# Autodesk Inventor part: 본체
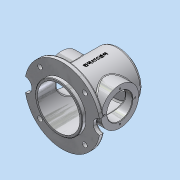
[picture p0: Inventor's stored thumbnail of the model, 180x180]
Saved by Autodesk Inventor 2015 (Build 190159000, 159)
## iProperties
Created: 2018-04
Part Number: 본체
Material: 알루미늄 6061
Document SubType Name: Modeling
Designer: Administrator
Density: 2.7 g/cm^3
Appearance: 알루미늄 - 평지
Mass: 1145.58 g
Surface Area: 1204.98 cm^2
Volume: 424.287 cm^3
Author: Administrator
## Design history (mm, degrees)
sketch "스케치1"
  geometry: 1 further point
sketch "스케치2"
  geometry: L1 (0, -64)-(0, 64); L2 (0, 64)-(-50, 64); L3 (-50, 64)-(-50, -64); L4 (-50, -64)-(0, -64); 2 further points
  constraints: 8 end point, 3 perpendicular, 1 coincident, 1 midpoint, 1 vertical
  dimensions: "d0" = 50 distance of L3.end L1.start; "d1" = 128 distance of L2.end L3.end
revolve "회전1" sketch "스케치2" stored, may be unused: angle "d2" = 90 deg
node "작업 평면1"
sketch "스케치3"
  geometry: C1 r 80 at (0, 0); 1 further point
  constraints: 1 centre point, 1 coincident
  dimensions: "d4" = 160 diameter of C1
extrude "돌출1" join sketch "스케치3" distance "d5" = 10; taper "d6" = 0 deg
sketch "스케치4"
  geometry: A1 r 80 centre (0, 0) between (-80, 0) and (80, 0) reference
  constraints: 2 horizontal alignment, 2 point on circle
hole "구멍1" sketch "스케치4" at (80, 0), (-80, 0) diameter "d7" = 30; stored, may be unused: countersink angle "d11" = 90 deg, drill point angle "d13" = 118 deg; dims "d8" = 6, "d9" = 4, "d10" = 2, "d12" = 8
sketch "스케치5" dims "d14" = 135
  geometry: L1 (0, 0)-(0, 102.247); L2 (0, 0)-(-71.221, 71.221); A1 r 80 centre (0, 0) between (-78.594, -14.934) and (78.594, -14.934) reference; 1 further point
  constraints: 4 end point, 1 coincident, 1 point on line, 1 vertical, 3 other
  dimensions: "d15" = 45 deg angle of L2 L1
hole "구멍2" sketch "스케치5" at (-47.73, 47.73) diameter "d16" = 10; stored, may be unused: countersink angle "d20" = 90 deg, drill point angle "d22" = 118 deg; dims "d17" = 6, "d18" = 4, "d19" = 2, "d21" = 8
fillet "모깎기1" dims "d26" = 3
sketch "스케치6"
  geometry: C1 r 50 at (0, 0) reference; C2 r 40 at (0, 0)
  constraints: 1 centre point, 1 coincident
  dimensions: "d27" = 80 diameter of C2
extrude "돌출2" join sketch "스케치6" distance "d28" = 5; taper "d29" = 0 deg
fillet "모깎기2" dims "d30" = 3
sketch "스케치7"
  geometry: L1 (0, -64)-(0, 69); L2 (0, 69)-(-27, 69); L3 (-27, 69)-(-27, 56); L4 (-27, 56)-(-45, 56); L5 (-45, 56)-(-45, -64); L6 (-45, -64)-(0, -64); L7 (40, 69)-(-40, 69) reference; 1 further point
  constraints: 12 end point, 5 perpendicular, 1 midpoint, 1 point on line, 1 vertical
  dimensions: "d31" = 133 distance of L1.start L1.end; "d32" = 45 distance of L5.end L1.start; "d33" = 27 distance of L1.end L2.end; "d34" = 120 distance of L4.end L5.end
revolve "회전2" sketch "스케치7" stored, may be unused: angle "d35" = 90 deg
chamfer "모따기1" distance "d36" = 1; stored, may be unused: second distance "d37" = 2, angle "d38" = 45 deg
node "작업 평면2"
sketch "스케치8"
  geometry: L1 (-56, 14.934)-(-56, 80) reference; C1 r 40 at (4, 0); 1 further point
  constraints: 1 centre point, 1 horizontal alignment
  dimensions: "d40" = 60 distance from line of C1.centre L1; "d41" = 80 diameter of C1
extrude "돌출3" join sketch "스케치8" stored distance "d42" = 124; taper "d43" = 0 deg
sketch "스케치9"
  geometry: C1 r 40 at (0, 0) reference; C2 r 27 at (0, 0); 1 further point
  constraints: 1 centre point, 1 coincident
  dimensions: "d44" = 54 diameter of C2
extrude "돌출4" cut sketch "스케치9" distance "d45" = 124; taper "d46" = 0 deg
fillet "모깎기3" dims "d47" = 3
chamfer "모따기2" distance "d48" = 1; stored, may be unused: second distance "d49" = 2, angle "d50" = 45 deg
sketch "스케치10" dims "d51" = 65
  geometry: C1 r 40 at (0, 0) reference; C2 r 28 at (0, 0) reference; 2 further points
  constraints: 2 vertical alignment, 1 coincident, 2 other
hole "구멍3" sketch "스케치10" at (0, -32.5) diameter "d52" = 3.242; stored, may be unused: countersink angle "d56" = 90 deg, drill point angle "d58" = 118 deg; dims "d53" = 8, "d54" = 4, "d55" = 2, "d57" = 10
sketch "스케치11" dims "d62" = 65
  geometry: C1 r 40 at (0, 0) reference; C2 r 28 at (0, 0) reference; 3 further points
  constraints: 2 vertical alignment, 1 coincident, 2 other
hole "구멍4" sketch "스케치11" at (0, 32.5) diameter "d63" = 3.242; stored, may be unused: countersink angle "d67" = 90 deg, drill point angle "d69" = 118 deg; dims "d64" = 8, "d65" = 4, "d66" = 2, "d68" = 10
node "작업 평면3"
sketch "스케치12"
  geometry: L1 (78.594, -56)-(-78.594, -56) reference; 2 further points
  constraints: 1 vertical alignment, 1 other
  dimensions: "d74" = 70 distance from line of L1 point (0, 14)
feature "엠보싱1" sketch "스케치12" dims "d0" = 50, "d1" = 128, "d75" = 0.5, "d76" = 0
fillet "모깎기4" dims "d77" = 3
fillet "모깎기5" dims "d78" = 3
fillet "모깎기6" dims "d79" = 5
node "솔리드1"
pattern_circular "원형 패턴1" dims angle "d24" = 360 deg
mirror "대칭1"
pattern_circular "원형 패턴2" dims angle "d60" = 360 deg
pattern_circular "원형 패턴3" dims angle "d71" = 360 deg
mirror "대칭2"
other parameters: "d3" = -8, "d39" = 62, "d73" = 136.25
